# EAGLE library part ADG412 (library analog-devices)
LC2MOS Precision Quad SPST Switches Source: http://www.analog.com/static/imported-files/data_sheets/ADG411_412_413.pdf
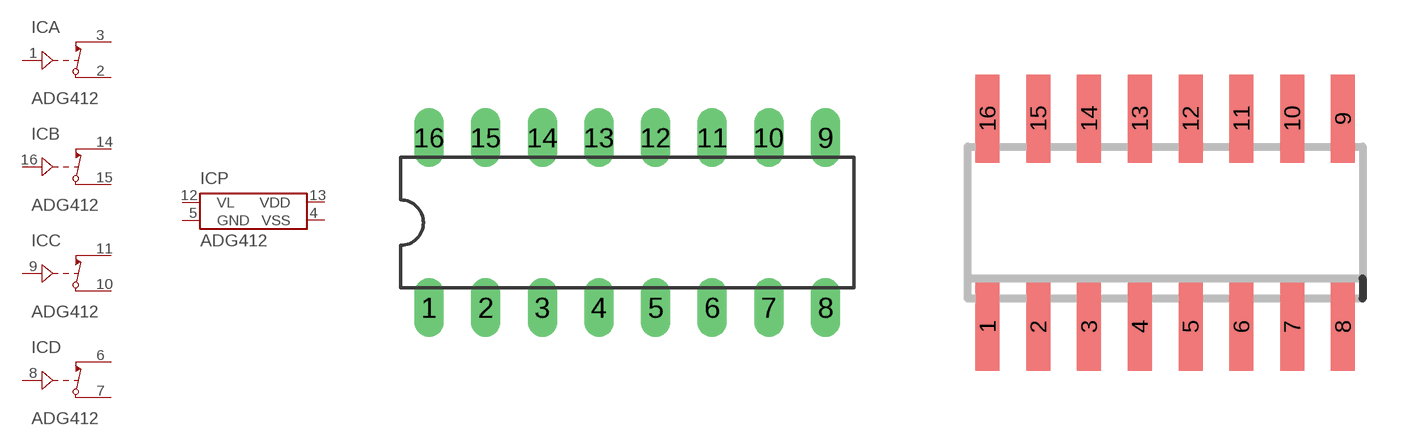
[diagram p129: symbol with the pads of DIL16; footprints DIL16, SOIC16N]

Designator prefix IC; gates A=ADG-SWITCH-OPEN B=ADG-SWITCH-OPEN C=ADG-SWITCH-OPEN D=ADG-SWITCH-OPEN P=PWR-VSS-VDD-GND-VL

## ADG412N (MF: ALTERA CORPORATION; MPN: ADG412TQ; OC_FARNELL: 1438704; OC_NEWARK: 09B7025)  [DIL16]
1  A:IN  in
2  A:D  pas
3  A:S  pas
4  P:VSS  pwr
5  P:GND  pwr
6  D:S  pas
7  D:D  pas
8  D:IN  in
9  C:IN  in
10  C:D  pas
11  C:S  pas
12  P:VL  pwr
13  P:VDD  pwr
14  B:S  pas
15  B:D  pas
16  B:IN  in

## ADG412R (MF: ALTERA CORPORATION; MPN: ADG412BRZ; OC_FARNELL: 1661021; OC_NEWARK: 59K1252)  [SOIC16N]
Pads as for DIL16

## ADG412RU (MF: ALTERA CORPORATION; MPN: ADG412BRU-REEL7; OC_FARNELL: unknown; OC_NEWARK: 59K1251)  [TSSOP16]
Pads as for DIL16

## Footprint DIL16 (pad centres in mm)
Dual In Line Package
drill 0.813 long: 1 -8.89,-3.81; 2 -6.35,-3.81; 3 -3.81,-3.81; 4 -1.27,-3.81; 5 1.27,-3.81; 6 3.81,-3.81; 7 6.35,-3.81; 8 8.89,-3.81; 9 8.89,3.81; 10 6.35,3.81; 11 3.81,3.81; 12 1.27,3.81; 13 -1.27,3.81; 14 -3.81,3.81; 15 -6.35,3.81; 16 -8.89,3.81

## Footprint SOIC16N (pad centres in mm)
SMALL OUTLINE INTEGRATED CIRCUIT
smd 0.6 x 2.2: 1 -4.445,-2.6; 2 -3.175,-2.6; 3 -1.905,-2.6; 4 -0.635,-2.6; 5 0.635,-2.6; 6 1.905,-2.6; 7 3.175,-2.6; 8 4.445,-2.6; 9 4.445,2.6; 10 3.175,2.6; 11 1.905,2.6; 12 0.635,2.6; 13 -0.635,2.6; 14 -1.905,2.6; 15 -3.175,2.6; 16 -4.445,2.6

## Footprint TSSOP16 (pad centres in mm)
16-Lead Thin Shrink Small Outline Package [TSSOP] (RU-16) Source: 8x ADG1408_1409.pdf
smd 0.9 x 0.35: 1 -2.875,2.275; 2 -2.875,1.625; 3 -2.875,0.975; 4 -2.875,0.325; 5 -2.875,-0.325; 6 -2.875,-0.975; 7 -2.875,-1.625; 8 -2.875,-2.275; 9 2.875,-2.275; 10 2.875,-1.625; 11 2.875,-0.975; 12 2.875,-0.325; 13 2.875,0.325; 14 2.875,0.975; 15 2.875,1.625; 16 2.875,2.275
